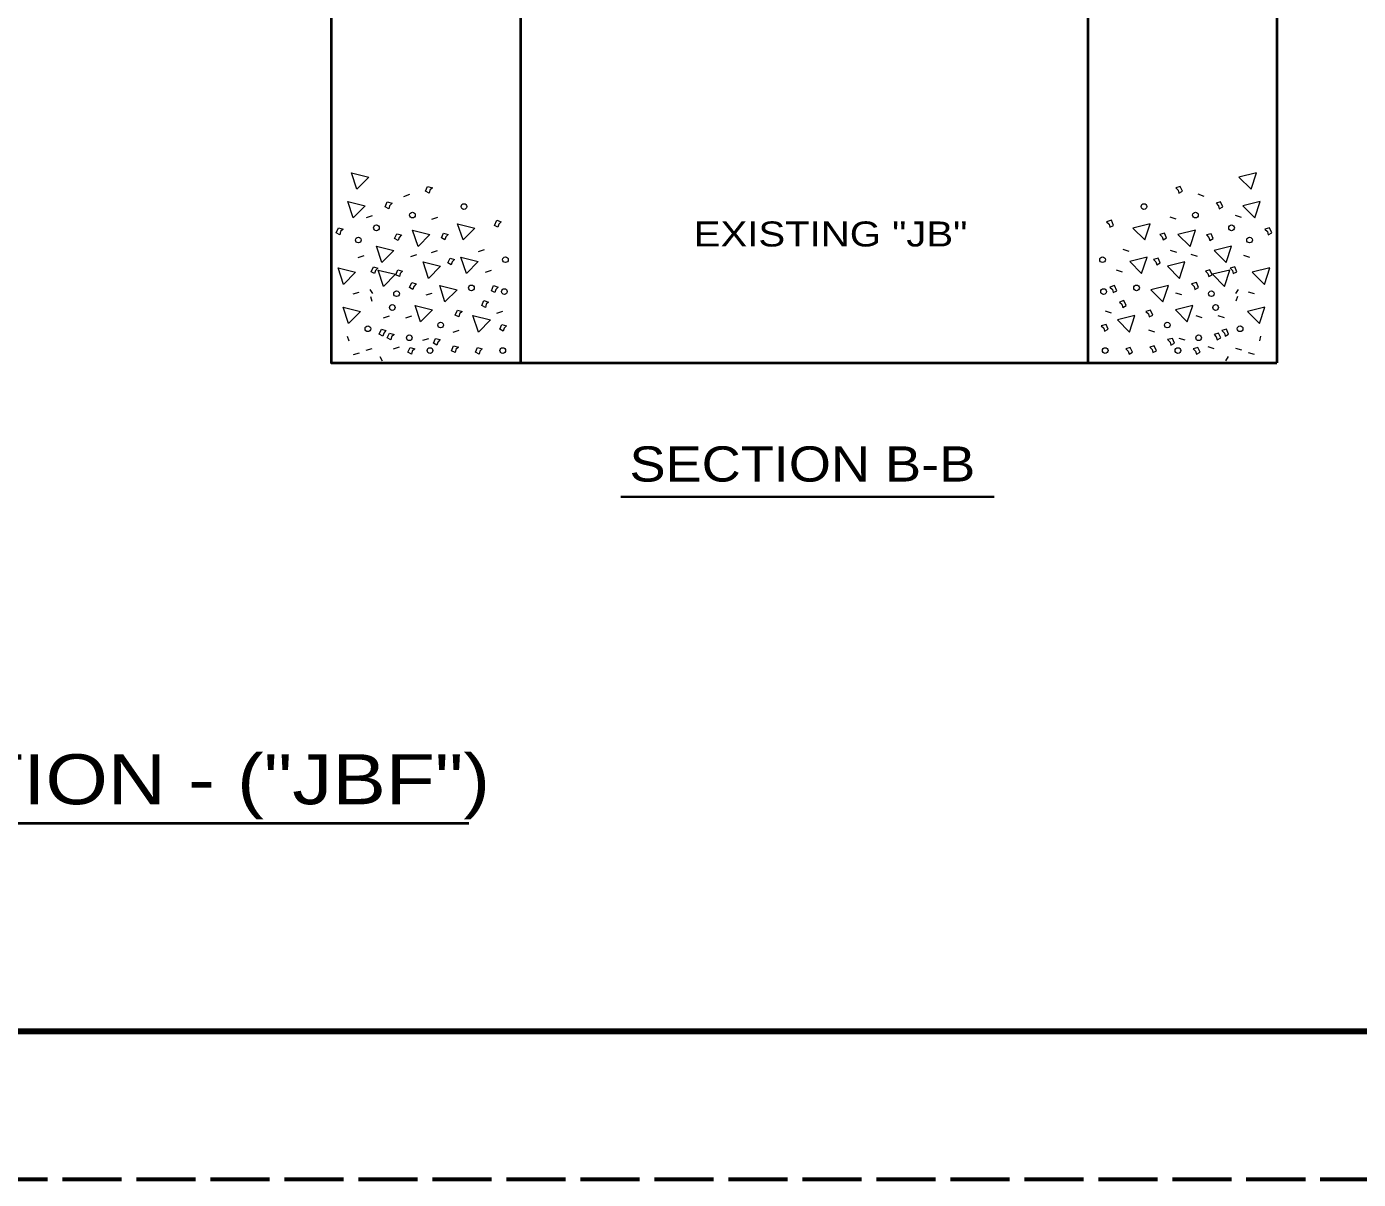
# Model space of a CAD drawing. Extents: x 312583 to 312853, y 144419 to 144586.
# Drawn here: x 312745.36 to 312785.86, y 144418.58 to 144453.62 of the extents above; entities that cross this region are included whole.
import ezdxf
from ezdxf.enums import TextEntityAlignment as Align

# ---------------------------------------------------------------- set-up
doc = ezdxf.new("R2010")
doc.units = 0
doc.header["$LTSCALE"] = 0.3
doc.linetypes.add('LONG_DASHED', pattern=[7.5, 6, -1.5])
doc.layers.add('1', color=7, linetype='Continuous', lineweight=40)
doc.layers.add('2', color=7, linetype='Continuous', lineweight=13)

msp = doc.modelspace()

# ---------------------------------------------------------------- linework, layer by layer
at = {"layer": '1'}
for p, q in [((312783.376, 144486.0501), (312783.376, 144443.4004)), ((312760.376, 144485.3294), (312760.376, 144443.4004)), ((312777.626, 144485.3294), (312777.626, 144443.4004))]:
    msp.add_line(p, q, dxfattribs=at)
at = {"layer": '1', "lineweight": 158}
msp.add_line((312616.5, 144423.0846), (312849, 144423.0846), dxfattribs=at)
at = {"layer": '1', "linetype": 'LONG_DASHED', "lineweight": 60}
msp.add_line((312851.75, 144418.5846), (312583.526, 144418.5846), dxfattribs=at)
msp.add_line((312851.75, 144418.5846), (312583.526, 144418.5846), dxfattribs=at)
at = {"layer": '1'}
msp.add_lwpolyline([(312754.626, 144486.0501), (312754.626, 144443.4004), (312783.376, 144443.4004)], dxfattribs=at)
at = {"layer": '2'}
for p, q in [((312756.834, 144448.4604), (312757.0104, 144448.5217)), ((312781.168, 144448.4604), (312780.984, 144448.5217)), ((312755.6994, 144447.8164), (312755.8834, 144447.8777)), ((312757.685, 144447.7704), (312757.869, 144447.8241)), ((312780.317, 144447.7704), (312780.133, 144447.8241)), ((312782.3027, 144447.8164), (312782.1187, 144447.8777)), ((312757.6697, 144446.7507), (312757.8537, 144446.8121)), ((312759.1034, 144446.7814), (312759.2874, 144446.8427)), ((312778.891, 144446.7814), (312778.707, 144446.8427)), ((312780.3324, 144446.7507), (312780.1484, 144446.8121)), ((312755.4387, 144446.6051), (312755.6227, 144446.6664)), ((312757.041, 144446.6357), (312757.225, 144446.6971)), ((312780.961, 144446.6357), (312780.777, 144446.6971)), ((312782.5557, 144446.6051), (312782.3717, 144446.6664)), ((312759.318, 144446.1527), (312759.502, 144446.2141)), ((312778.684, 144446.1527), (312778.5, 144446.2141)), ((312755.293, 144445.4934), (312755.477, 144445.5471)), ((312755.799, 144445.6314), (312755.8834, 144445.5087)), ((312757.5087, 144445.4627), (312757.6927, 144445.5164)), ((312780.4934, 144445.4627), (312780.3094, 144445.5164)), ((312782.203, 144445.6314), (312782.1187, 144445.5087)), ((312782.7014, 144445.4934), (312782.5174, 144445.5471)), ((312755.822, 144445.4167), (312755.8604, 144445.2787)), ((312782.18, 144445.4167), (312782.134, 144445.2787)), ((312756.213, 144444.7651), (312756.397, 144444.8264)), ((312756.8954, 144444.7651), (312757.0794, 144444.8264)), ((312759.6554, 144444.9107), (312759.8394, 144444.9721)), ((312778.3467, 144444.9107), (312778.1627, 144444.9721)), ((312781.1067, 144444.7651), (312780.9227, 144444.8264)), ((312781.7814, 144444.7651), (312781.5974, 144444.8264)), ((312758.329, 144444.3281), (312758.513, 144444.3894)), ((312779.6654, 144444.3281), (312779.489, 144444.3894)), ((312755.109, 144444.2131), (312755.155, 144444.0674)), ((312756.5197, 144443.8297), (312756.7037, 144443.8911)), ((312757.409, 144444.0904), (312757.593, 144444.1441)), ((312780.5854, 144444.0904), (312780.409, 144444.1441)), ((312781.4747, 144443.8297), (312781.2907, 144443.8911)), ((312782.8854, 144444.2131), (312782.847, 144444.0674)), ((312755.3007, 144443.6534), (312755.4847, 144443.7071)), ((312755.684, 144443.7837), (312755.868, 144443.8374)), ((312756.1057, 144443.5921), (312756.1747, 144443.4617)), ((312781.8964, 144443.5921), (312781.8197, 144443.4617)), ((312782.318, 144443.7837), (312782.134, 144443.8374)), ((312782.7014, 144443.6534), (312782.5174, 144443.7071))]:
    msp.add_line(p, q, dxfattribs=at)
at = {"layer": '2', "lineweight": 35}
msp.add_line((312763.4336, 144439.3294), (312774.7838, 144439.3294), dxfattribs=at)
at = {"layer": '2', "lineweight": 40}
msp.add_line((312655.2181, 144429.4108), (312758.809, 144429.4108), dxfattribs=at)
at = {"layer": '2'}
for points in [[(312755.7684, 144449.0431), (312755.408, 144448.6827), (312755.2394, 144449.1734)], [(312782.226, 144449.0431), (312782.594, 144448.6827), (312782.755, 144449.1734)], [(312757.6237, 144448.6444), (312757.6007, 144448.5601), (312757.4934, 144448.6137), (312757.5547, 144448.7594), (312757.7004, 144448.7211)], [(312780.3784, 144448.6444), (312780.4014, 144448.5601), (312780.5087, 144448.6137), (312780.4397, 144448.7594), (312780.3017, 144448.7211)], [(312755.6534, 144448.1767), (312755.293, 144447.8087), (312755.1244, 144448.3071)], [(312756.397, 144448.1767), (312756.374, 144448.0847), (312756.2667, 144448.1461), (312756.328, 144448.2917), (312756.4737, 144448.2534)], [(312781.605, 144448.1767), (312781.628, 144448.0847), (312781.7354, 144448.1461), (312781.6664, 144448.2917), (312781.5284, 144448.2534)], [(312782.341, 144448.1767), (312782.709, 144447.8087), (312782.87, 144448.3071)], [(312758.996, 144447.4944), (312758.6357, 144447.1341), (312758.467, 144447.6247)], [(312759.7244, 144447.6171), (312759.6937, 144447.5251), (312759.5864, 144447.5787), (312759.6554, 144447.7321), (312759.7934, 144447.6861)], [(312778.2777, 144447.6171), (312778.3007, 144447.5251), (312778.408, 144447.5787), (312778.3467, 144447.7321), (312778.201, 144447.6861)], [(312778.9984, 144447.4944), (312779.3664, 144447.1341), (312779.5274, 144447.6247)], [(312754.9097, 144447.3871), (312754.8867, 144447.2951), (312754.7794, 144447.3564), (312754.8407, 144447.5021), (312754.9864, 144447.4637)], [(312756.6884, 144447.2107), (312756.6577, 144447.1187), (312756.5504, 144447.1801), (312756.6194, 144447.3257), (312756.7574, 144447.2874)], [(312757.6237, 144447.3027), (312757.2634, 144446.9347), (312757.0947, 144447.4331)], [(312758.1067, 144447.2261), (312758.0837, 144447.1341), (312757.9764, 144447.1954), (312758.0377, 144447.3411), (312758.1834, 144447.3027)], [(312779.8954, 144447.2261), (312779.9184, 144447.1341), (312780.0257, 144447.1954), (312779.9567, 144447.3411), (312779.8187, 144447.3027)], [(312780.3707, 144447.3027), (312780.7387, 144446.9347), (312780.8997, 144447.4331)], [(312781.3137, 144447.2107), (312781.3367, 144447.1187), (312781.444, 144447.1801), (312781.3827, 144447.3257), (312781.237, 144447.2874)], [(312783.0924, 144447.3871), (312783.1154, 144447.2951), (312783.2227, 144447.3564), (312783.1537, 144447.5021), (312783.0157, 144447.4637)], [(312756.5274, 144446.8197), (312756.167, 144446.4517), (312755.9984, 144446.9501)], [(312781.467, 144446.8197), (312781.835, 144446.4517), (312781.996, 144446.9501)], [(312755.9677, 144446.2064), (312755.9447, 144446.1144), (312755.8374, 144446.1681), (312755.9064, 144446.3214), (312756.0444, 144446.2754)], [(312757.9457, 144446.3367), (312757.5854, 144445.9687), (312757.4167, 144446.4671)], [(312758.2984, 144446.4671), (312758.2754, 144446.3751), (312758.168, 144446.4364), (312758.237, 144446.5821), (312758.375, 144446.5437)], [(312759.0957, 144446.4824), (312758.7354, 144446.1144), (312758.5667, 144446.6127)], [(312778.9064, 144446.4824), (312779.2667, 144446.1144), (312779.4354, 144446.6127)], [(312779.696, 144446.4671), (312779.7267, 144446.3751), (312779.834, 144446.4364), (312779.765, 144446.5821), (312779.627, 144446.5437)], [(312780.0487, 144446.3367), (312780.4167, 144445.9687), (312780.5777, 144446.4671)], [(312782.0267, 144446.2064), (312782.0497, 144446.1144), (312782.1647, 144446.1681), (312782.0957, 144446.3214), (312781.9577, 144446.2754)], [(312755.362, 144446.1527), (312755.0017, 144445.7847), (312754.833, 144446.2831)], [(312756.581, 144446.0914), (312756.213, 144445.7234), (312756.052, 144446.2217)], [(312756.719, 144446.1144), (312756.696, 144446.0224), (312756.5887, 144446.0761), (312756.65, 144446.2294), (312756.7957, 144446.1911)], [(312781.283, 144446.1144), (312781.306, 144446.0224), (312781.4134, 144446.0761), (312781.3444, 144446.2294), (312781.2064, 144446.1911)], [(312781.421, 144446.0914), (312781.789, 144445.7234), (312781.95, 144446.2217)], [(312782.6324, 144446.1527), (312783.0004, 144445.7847), (312783.1614, 144446.2831)], [(312757.1407, 144445.7234), (312757.11, 144445.6314), (312757.0027, 144445.6927), (312757.0717, 144445.8384), (312757.2097, 144445.8001)], [(312758.4517, 144445.6237), (312758.0837, 144445.2557), (312757.9227, 144445.7541)], [(312759.6247, 144445.6314), (312759.6017, 144445.5394), (312759.4944, 144445.5931), (312759.5557, 144445.7464), (312759.7014, 144445.7004)], [(312778.3774, 144445.6314), (312778.4004, 144445.5394), (312778.5077, 144445.5931), (312778.4387, 144445.7464), (312778.3007, 144445.7004)], [(312779.5504, 144445.6237), (312779.9107, 144445.2557), (312780.0794, 144445.7541)], [(312780.8614, 144445.7234), (312780.8844, 144445.6314), (312780.9917, 144445.6927), (312780.9304, 144445.8384), (312780.7847, 144445.8001)], [(312755.5154, 144444.9644), (312755.1474, 144444.5964), (312754.9864, 144445.0947)], [(312757.708, 144445.0104), (312757.34, 144444.6424), (312757.179, 144445.1407)], [(312759.3334, 144445.1791), (312759.3104, 144445.0871), (312759.203, 144445.1407), (312759.2644, 144445.2941), (312759.41, 144445.2481)], [(312778.6687, 144445.1791), (312778.6917, 144445.0871), (312778.799, 144445.1407), (312778.73, 144445.2941), (312778.592, 144445.2481)], [(312780.294, 144445.0104), (312780.6544, 144444.6424), (312780.823, 144445.1407)], [(312782.4867, 144444.9644), (312782.8547, 144444.5964), (312783.0157, 144445.0947)], [(312758.5284, 144444.8877), (312758.5054, 144444.7957), (312758.398, 144444.8494), (312758.4594, 144445.0027), (312758.605, 144444.9644)], [(312759.4637, 144444.7037), (312759.1034, 144444.3357), (312758.9347, 144444.8341)], [(312778.5307, 144444.7037), (312778.8987, 144444.3357), (312779.0597, 144444.8341)], [(312779.4737, 144444.8877), (312779.4967, 144444.7957), (312779.604, 144444.8494), (312779.535, 144445.0027), (312779.397, 144444.9644)], [(312756.2207, 144444.3051), (312756.19, 144444.2131), (312756.0827, 144444.2744), (312756.1517, 144444.4201), (312756.2897, 144444.3817)], [(312756.4584, 144444.1901), (312756.4354, 144444.0981), (312756.328, 144444.1594), (312756.397, 144444.3051), (312756.535, 144444.2667)], [(312759.8854, 144444.4507), (312759.8547, 144444.3587), (312759.7474, 144444.4201), (312759.8164, 144444.5657), (312759.9544, 144444.5274)], [(312778.1167, 144444.4507), (312778.1397, 144444.3587), (312778.247, 144444.4201), (312778.1857, 144444.5657), (312778.04, 144444.5274)], [(312781.536, 144444.1901), (312781.5667, 144444.0981), (312781.674, 144444.1594), (312781.605, 144444.3051), (312781.467, 144444.2667)], [(312781.7814, 144444.3051), (312781.8044, 144444.2131), (312781.9117, 144444.2744), (312781.8504, 144444.4201), (312781.7047, 144444.3817)], [(312757.087, 144443.7531), (312757.064, 144443.6611), (312756.9567, 144443.7224), (312757.0257, 144443.8681), (312757.1637, 144443.8297)], [(312757.8614, 144444.0291), (312757.8384, 144443.9371), (312757.731, 144443.9984), (312757.8, 144444.1441), (312757.938, 144444.1057)], [(312758.4134, 144443.8067), (312758.3904, 144443.7147), (312758.283, 144443.7684), (312758.3444, 144443.9217), (312758.49, 144443.8757)], [(312759.1417, 144443.7531), (312759.1187, 144443.6611), (312759.0114, 144443.7224), (312759.0727, 144443.8681), (312759.2184, 144443.8297)], [(312778.8604, 144443.7531), (312778.8834, 144443.6611), (312778.9907, 144443.7224), (312778.9217, 144443.8681), (312778.7837, 144443.8297)], [(312779.5887, 144443.8067), (312779.6117, 144443.7147), (312779.719, 144443.7684), (312779.65, 144443.9217), (312779.512, 144443.8757)], [(312780.133, 144444.0291), (312780.156, 144443.9371), (312780.2634, 144443.9984), (312780.202, 144444.1441), (312780.0564, 144444.1057)], [(312780.9074, 144443.7531), (312780.938, 144443.6611), (312781.0454, 144443.7224), (312780.9764, 144443.8681), (312780.8384, 144443.8297)]]:
    msp.add_lwpolyline(points, close=True, dxfattribs=at)
for centre in [(312757.0951, 144447.891), (312758.661, 144448.1497), (312779.3372, 144448.1497), (312780.9032, 144447.891), (312755.9978, 144447.5038), (312782.0005, 144447.5038), (312755.4487, 144447.133), (312782.5496, 144447.133), (312759.9202, 144446.535), (312778.078, 144446.535), (312756.6111, 144445.5019), (312758.8872, 144445.6792), (312759.8886, 144445.5661), (312778.1096, 144445.5661), (312779.1111, 144445.6792), (312781.3871, 144445.5019), (312756.4817, 144445.0821), (312781.5165, 144445.0821), (312755.739, 144444.4362), (312757.9509, 144444.5493), (312780.0474, 144444.5493), (312782.2592, 144444.4362), (312756.9983, 144444.1621), (312781, 144444.1621), (312757.6279, 144443.774), (312759.8397, 144443.774), (312778.1585, 144443.774), (312780.3703, 144443.774)]:
    msp.add_circle(centre, 0.0865, dxfattribs=at)

# ---------------------------------------------------------------- texts
at = {"layer": '2', "width": 1.2}
msp.add_text('EXISTING "JB"', height=0.76, dxfattribs=at).set_placement((312765.6482, 144446.9367))
at = {"layer": '2'}
for s, height, width, p in [('SECTION B-B', 1.07, 1.15, (312768.95, 144439.7915)), ('CAPPING DETAILS FOR EXTENSIONS OF EXISTING JUNCTION BOX FOUNDATION - ("JBF")', 1.52, 1.2, (312706.6171, 144429.9842))]:
    msp.add_text(s, height=height, dxfattribs=dict(at, width=width)).set_placement(p, align=Align.CENTER)

doc.saveas('drawing.dxf')
